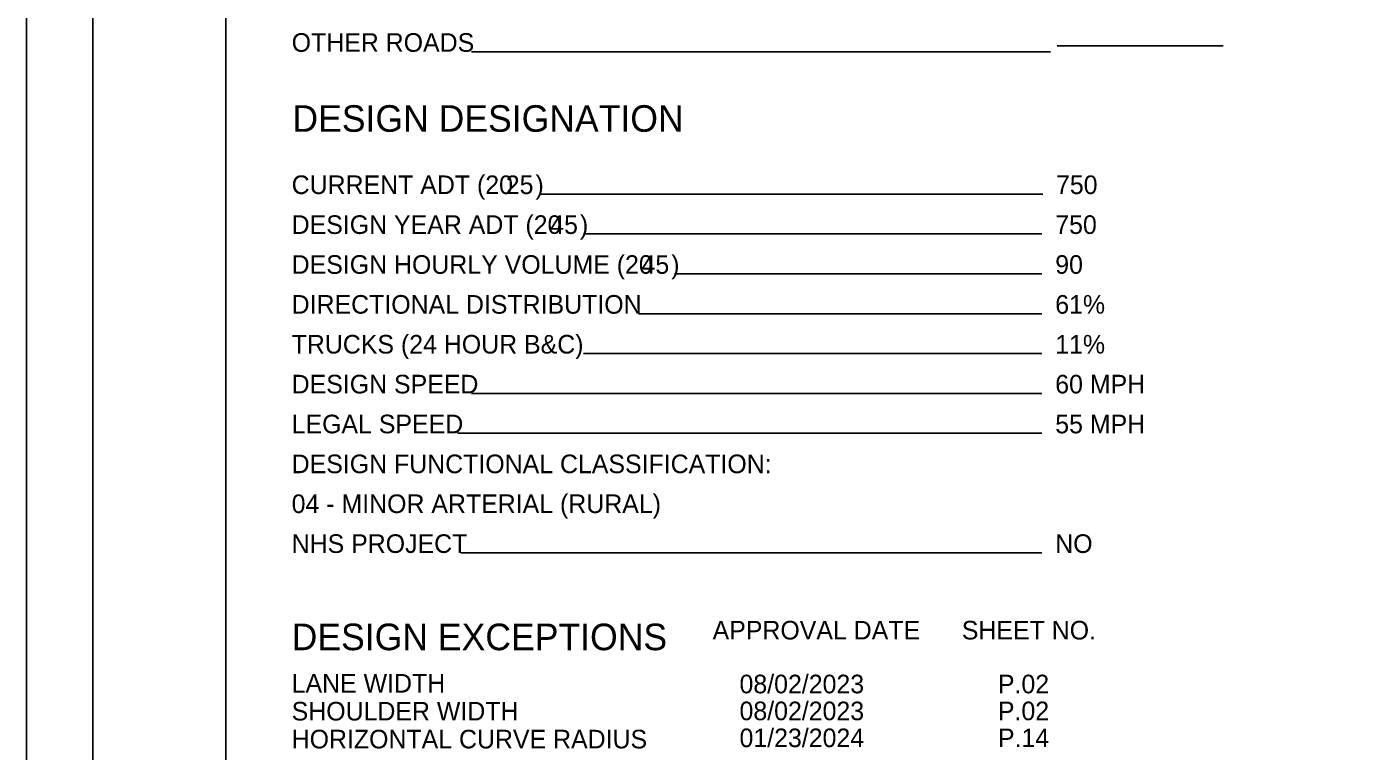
# Model space of a CAD drawing. Extents: x -3.3 to 34, y 0 to 56.8.
# Drawn here: x 0 to 9.95, y 5.61 to 11.07 of the extents above; entities that cross this region are included whole.
import ezdxf

# ---------------------------------------------------------------- set-up
doc = ezdxf.new("R2010")
doc.units = 0
for name, color, linetype in [('SH_Border', 7, 'Continuous'), ('SH_Cut_Line', 7, 'Continuous'), ('SH_Data', 7, 'Continuous'), ('SH_Major_Grid_Line', 7, 'Continuous')]:
    doc.layers.add(name, color=color, linetype=linetype)

msp = doc.modelspace()

# ---------------------------------------------------------------- linework, layer by layer
at = {"layer": 'SH_Border'}
msp.add_lwpolyline([(0, 0), (34, 0), (34, 22), (0, 22)], close=True, dxfattribs=at)
at = {"layer": 'SH_Cut_Line'}
for points in [[(0.5, 21.5), (1.5, 21.5), (1.5, 0.5), (0.5, 0.5)], [(1.5, 21.5), (33.5, 21.5), (33.5, 0.5), (1.5, 0.5)]]:
    msp.add_lwpolyline(points, close=True, dxfattribs=at)
at = {"layer": 'SH_Data'}
for p, q in [((7.7, 10.8767), (3.3471, 10.8767)), ((9, 10.9223), (7.75, 10.9223)), ((7.6424, 9.8062), (3.871, 9.8062)), ((7.6368, 9.5062), (4.1885, 9.5062)), ((7.6368, 9.2062), (4.8723, 9.2062)), ((7.6368, 8.9062), (4.6037, 8.9062)), ((7.6368, 8.6062), (4.1885, 8.6062)), ((7.6368, 8.3062), (3.346, 8.3062)), ((7.6368, 8.0062), (3.2422, 8.0062)), ((7.6368, 7.1062), (3.2669, 7.1062))]:
    msp.add_line(p, q, dxfattribs=at)

# ---------------------------------------------------------------- texts
msp.add_text('DESIGN DESIGNATION', height=0.2, dxfattribs=at).set_placement((2, 10.2747))
at = {"layer": 'SH_Major_Grid_Line'}
for s, height, p in [('OTHER ROADS', 0.14, (1.9944, 10.8767)), ('CURRENT ADT (20', 0.14, (1.9944, 9.8062)), (')', 0.14, (3.8282, 9.8062)), ('25', 0.14, (3.6047, 9.8062)), ('750   ', 0.14, (7.7424, 9.8062)), ('DESIGN YEAR ADT (20', 0.14, (1.9944, 9.5062)), (')', 0.14, (4.1625, 9.5062)), ('45', 0.14, (3.939, 9.5062)), ('750   ', 0.14, (7.7368, 9.5062)), ('DESIGN HOURLY VOLUME (20', 0.14, (1.9944, 9.2062)), (')', 0.14, (4.8488, 9.2062)), ('45', 0.14, (4.6254, 9.2062)), ('90    ', 0.14, (7.7368, 9.2062)), ('DIRECTIONAL DISTRIBUTION', 0.14, (1.9944, 8.9062)), ('61%   ', 0.14, (7.7368, 8.9062)), ('TRUCKS (24 HOUR B&C)', 0.14, (1.9944, 8.6062)), ('11%   ', 0.14, (7.7368, 8.6062)), ('DESIGN SPEED', 0.14, (1.9944, 8.3062)), ('60 MPH', 0.14, (7.7368, 8.3062)), ('LEGAL SPEED', 0.14, (1.9944, 8.0062)), ('55 MPH', 0.14, (7.7368, 8.0062)), ('DESIGN FUNCTIONAL CLASSIFICATION:', 0.14, (1.9944, 7.7062)), ('04 - MINOR ARTERIAL (RURAL)                     ', 0.14, (1.9944, 7.4062)), ('NHS PROJECT', 0.14, (1.9944, 7.1062)), ('NO    ', 0.14, (7.7368, 7.1062)), ('DESIGN EXCEPTIONS', 0.2, (1.9944, 6.3744)), ('APPROVAL DATE', 0.14, (5.1601, 6.455)), ('SHEET NO. ', 0.14, (7.0342, 6.455)), ('LANE WIDTH', 0.14, (1.9944, 6.0556)), ('08/02/2023', 0.14, (5.3625, 6.05)), ('P.02', 0.14, (7.3056, 6.05)), ('SHOULDER WIDTH', 0.14, (1.9944, 5.8456)), ('08/02/2023', 0.14, (5.3625, 5.8475)), ('P.02', 0.14, (7.3056, 5.8475)), ('HORIZONTAL CURVE RADIUS', 0.14, (1.9944, 5.6356)), ('01/23/2024', 0.14, (5.3625, 5.645)), ('P.14', 0.14, (7.306, 5.645))]:
    msp.add_text(s, height=height, dxfattribs=at).set_placement(p)

doc.saveas('drawing.dxf')
